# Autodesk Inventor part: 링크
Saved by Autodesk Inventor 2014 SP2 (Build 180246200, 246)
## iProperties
Created: 2025-07
Part Number: 링크
Material: Generic
Document SubType Name: Modeling
Designer: Administrator
Density: 1 g/cm^3
Appearance: Default
Author: Administrator
Author: jhkim
Creation Date: 2025-06-11
Sending System: Autodesk Inventor 2026
Preprocessor: ST-DEVELOPER v20.1
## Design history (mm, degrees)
node "링크1"
node "솔리드1"
node "기준1"
